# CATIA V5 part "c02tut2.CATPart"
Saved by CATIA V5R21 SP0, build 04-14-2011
Part number: c02tut2
Bounding box of the stored display mesh (mm): x 0 to 0, y -60 to 60, z -50 to 50
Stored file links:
  D:\CATIA V5R21 E-RESOURCES\CATIA-V5R21\catia-v5r21-prt\c02-catia-v5r21-prt\catia-v5r21-tut-2.CATPart
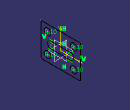
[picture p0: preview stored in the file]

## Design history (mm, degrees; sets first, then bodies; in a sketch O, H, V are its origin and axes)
Body1 (main body)
  Sketch1 on yz-plane, origin (0, 0, 0), H (0, 1, 0), V (0, 0, 1)
    line L1 (-60, -50) -> (60, -50)
    line L2 (60, -50) -> (60, 50)
    line L3 (60, 50) -> (-60, 50)
    line L4 (-60, 50) -> (-60, -50)
    line L5 (-30, 10) -> (30, 10)
    arc A1 centre (30, 0) radius 10 from (30, 10) to (30, -10) cw
    line L6 (30, -10) -> (-30, -10)
    arc A2 centre (-30, 0) radius 10 from (-30, -10) to (-30, 10) cw
    circle A3 centre (40, 30) radius 10
    circle A4 centre (40, -30) radius 10
    circle A5 centre (-40, 30) radius 10
    circle A6 centre (-40, -30) radius 10
    radius A3 = 10
    radius A4 = 10
    radius A5 = 10
    radius A6 = 10
    horizontal: L1 H, L3 H, L5 H
    vertical: L2 V, L4 V
    tangency: A1 L5, L6 A1, A2 L5, A2 L6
